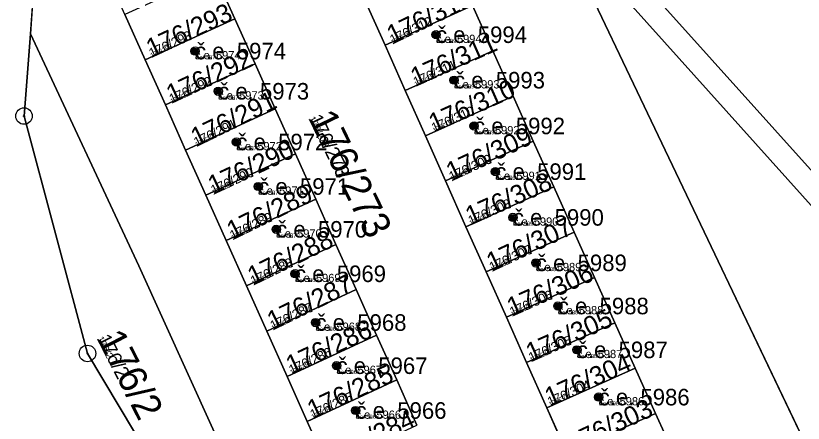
# Model space of a CAD drawing. Extents: x -759873 to -758487, y -975024 to -973516.
# Drawn here: x -759809.34 to -759761.69, y -974992.03 to -974967.38 of the extents above; entities that cross this region are included whole.
import ezdxf

# ---------------------------------------------------------------- set-up
doc = ezdxf.new("R2010")
doc.units = 0
for name, color, linetype in [('KAT_01_hranice KU', 7, 'Continuous'), ('KAT_02_hranice parcel', 7, 'Continuous'), ('KAT_03_1000_st čísla parcelní', 7, 'Continuous'), ('KAT_03_1000_čísla parcelní', 7, 'Continuous'), ('KAT_03_1000_čísla popisná', 7, 'Continuous'), ('KAT_03_250_st čísla parcelní', 7, 'Continuous'), ('KAT_03_250_čísla parcelní', 7, 'Continuous'), ('KAT_03_250_čísla popisná', 7, 'Continuous'), ('KAT_03_500_st čísla parcelní', 7, 'Continuous'), ('KAT_03_500_čísla parcelní', 7, 'Continuous'), ('KAT_03_500_čísla popisná', 7, 'Continuous'), ('KAT_07_1000_značky budov', 7, 'Continuous'), ('KAT_07_250_značky budov', 7, 'Continuous'), ('KAT_07_500_značky budov', 7, 'Continuous'), ('KAT_11_značky bodu BP', 7, 'Continuous'), ('KAT_14_plocha_budovy', 7, 'Continuous'), ('KAT_14_plocha_pozemek', 7, 'Continuous')]:
    doc.layers.add(name, color=color, linetype=linetype)

msp = doc.modelspace()

# ---------------------------------------------------------------- linework, layer by layer
at = {"layer": 'KAT_01_hranice KU'}
msp.add_lwpolyline([(-759803.85, -974931.39), (-759806.32, -974944.72), (-759806.02, -974945.39), (-759806.48, -974945.6), (-759806.7, -974946.76), (-759806.89, -974949.09), (-759807.18, -974952.49), (-759807.46, -974955.95), (-759807.76, -974956.08), (-759807.52, -974956.62), (-759808.2, -974964.8), (-759808.44, -974968.47), (-759808.84, -974973.45), (-759805, -974987.81), (-759801.16, -974994.22)], dxfattribs=at)
at = {"layer": 'KAT_02_hranice parcel'}
for p, q in [((-759776.67, -974961.64), (-759756.15, -975004.6)), ((-759808.44, -974968.47), (-759808.2, -974964.8)), ((-759797.31, -974964.83), (-759796.09, -974967.56)), ((-759786.99, -974969.17), (-759788.22, -974966.42)), ((-759781.71, -974966.77), (-759786.99, -974969.17)), ((-759781.71, -974966.77), (-759780.48, -974969.51)), ((-759801.51, -974970.04), (-759802.73, -974967.31)), ((-759796.09, -974967.56), (-759801.51, -974970.04)), ((-759796.09, -974967.56), (-759794.86, -974970.29)), ((-759785.77, -974971.91), (-759786.99, -974969.17)), ((-759780.48, -974969.51), (-759785.77, -974971.91)), ((-759780.48, -974969.51), (-759779.24, -974972.25)), ((-759800.28, -974972.78), (-759801.51, -974970.04)), ((-759794.86, -974970.29), (-759800.28, -974972.78)), ((-759794.86, -974970.29), (-759793.64, -974973.01)), ((-759784.55, -974974.65), (-759785.77, -974971.91)), ((-759779.24, -974972.25), (-759784.55, -974974.65)), ((-759779.24, -974972.25), (-759778.03, -974974.96)), ((-759799.06, -974975.51), (-759800.28, -974972.78)), ((-759793.64, -974973.01), (-759799.06, -974975.51)), ((-759793.64, -974973.01), (-759792.42, -974975.74)), ((-759783.34, -974977.36), (-759784.55, -974974.65)), ((-759778.03, -974974.96), (-759783.34, -974977.36)), ((-759778.03, -974974.96), (-759776.78, -974977.74)), ((-759797.83, -974978.23), (-759799.06, -974975.51)), ((-759792.42, -974975.74), (-759797.83, -974978.23)), ((-759792.42, -974975.74), (-759791.19, -974978.48)), ((-759782.1, -974980.14), (-759783.34, -974977.36)), ((-759776.78, -974977.74), (-759782.1, -974980.14)), ((-759776.78, -974977.74), (-759775.55, -974980.48)), ((-759796.6, -974980.98), (-759797.83, -974978.23)), ((-759791.19, -974978.48), (-759796.6, -974980.98)), ((-759791.19, -974978.48), (-759789.97, -974981.21)), ((-759780.87, -974982.88), (-759782.1, -974980.14)), ((-759775.55, -974980.48), (-759780.87, -974982.88)), ((-759775.55, -974980.48), (-759774.32, -974983.22)), ((-759795.38, -974983.71), (-759796.6, -974980.98)), ((-759789.97, -974981.21), (-759795.38, -974983.71)), ((-759789.97, -974981.21), (-759788.74, -974983.95)), ((-759779.65, -974985.62), (-759780.87, -974982.88)), ((-759774.32, -974983.22), (-759779.65, -974985.62)), ((-759774.32, -974983.22), (-759773.09, -974985.95)), ((-759794.15, -974986.46), (-759795.38, -974983.71)), ((-759788.74, -974983.95), (-759794.15, -974986.46)), ((-759788.74, -974983.95), (-759787.51, -974986.7)), ((-759778.44, -974988.35), (-759779.65, -974985.62)), ((-759773.09, -974985.95), (-759778.44, -974988.35)), ((-759773.09, -974985.95), (-759771.86, -974988.69)), ((-759792.91, -974989.21), (-759794.15, -974986.46)), ((-759787.51, -974986.7), (-759792.91, -974989.21)), ((-759787.51, -974986.7), (-759786.29, -974989.41)), ((-759777.21, -974991.09), (-759778.44, -974988.35)), ((-759771.86, -974988.69), (-759777.21, -974991.09)), ((-759771.86, -974988.69), (-759770.63, -974991.44)), ((-759791.7, -974991.92), (-759792.91, -974989.21)), ((-759786.29, -974989.41), (-759791.7, -974991.92)), ((-759786.29, -974989.41), (-759785.07, -974992.14)), ((-759775.98, -974993.84), (-759777.21, -974991.09)), ((-759770.63, -974991.44), (-759775.98, -974993.84)), ((-759770.63, -974991.44), (-759769.39, -974994.19)), ((-759790.47, -974994.66), (-759791.7, -974991.92))]:
    msp.add_line(p, q, dxfattribs=at)
for points in [[(-759776.67, -974961.64), (-759760.85, -974979.26), (-759749.8, -974991.38)], [(-759740.23, -974999.88), (-759748.8, -974990.42), (-759759.81, -974978.29), (-759770.81, -974966.03)], [(-759801.16, -974994.22), (-759805, -974987.81), (-759808.84, -974973.45), (-759808.44, -974968.47)], [(-759786.86, -975015.6), (-759801.9, -974982.51), (-759808.44, -974968.47)]]:
    msp.add_lwpolyline(points, dxfattribs=at)
at = {"layer": 'KAT_03_1000_čísla popisná'}
for centre in [(-759783.91, -974968.53), (-759798.49, -974969.52), (-759782.82, -974971.28), (-759797.09, -974971.95), (-759781.61, -974974.05), (-759795.99, -974975.02), (-759780.32, -974976.81), (-759794.67, -974977.71), (-759779.26, -974979.58), (-759793.58, -974980.3), (-759777.87, -974982.33), (-759792.44, -974982.99), (-759776.54, -974984.94), (-759791.2, -974985.94), (-759775.39, -974987.59), (-759789.93, -974988.55), (-759774.07, -974990.45), (-759788.78, -974991.26)]:
    msp.add_circle(centre, 0.25, dxfattribs=at)
at = {"layer": 'KAT_03_250_čísla popisná'}
for centre in [(-759783.91, -974968.53), (-759798.49, -974969.52), (-759782.82, -974971.28), (-759797.09, -974971.95), (-759781.61, -974974.05), (-759795.99, -974975.02), (-759780.32, -974976.81), (-759794.67, -974977.71), (-759779.26, -974979.58), (-759793.58, -974980.3), (-759777.87, -974982.33), (-759792.44, -974982.99), (-759776.54, -974984.94), (-759791.2, -974985.94), (-759775.39, -974987.59), (-759789.93, -974988.55), (-759774.07, -974990.45), (-759788.78, -974991.26)]:
    msp.add_circle(centre, 0.0625, dxfattribs=at)
at = {"layer": 'KAT_03_500_čísla popisná'}
for centre in [(-759783.91, -974968.53), (-759798.49, -974969.52), (-759782.82, -974971.28), (-759797.09, -974971.95), (-759781.61, -974974.05), (-759795.99, -974975.02), (-759780.32, -974976.81), (-759794.67, -974977.71), (-759779.26, -974979.58), (-759793.58, -974980.3), (-759777.87, -974982.33), (-759792.44, -974982.99), (-759776.54, -974984.94), (-759791.2, -974985.94), (-759775.39, -974987.59), (-759789.93, -974988.55), (-759774.07, -974990.45), (-759788.78, -974991.26)]:
    msp.add_circle(centre, 0.125, dxfattribs=at)
at = {"layer": 'KAT_07_1000_značky budov'}
for centre in [(-759783.917, -974968.529), (-759798.497, -974969.519), (-759782.827, -974971.279), (-759797.097, -974971.949), (-759781.617, -974974.049), (-759795.997, -974975.019), (-759780.327, -974976.809), (-759794.677, -974977.709), (-759779.267, -974979.579), (-759793.587, -974980.299), (-759777.877, -974982.329), (-759792.447, -974982.989), (-759776.547, -974984.939), (-759791.207, -974985.939), (-759775.397, -974987.589), (-759789.937, -974988.549), (-759774.077, -974990.449), (-759788.787, -974991.259)]:
    msp.add_circle(centre, 0.175, dxfattribs=at)
at = {"layer": 'KAT_07_250_značky budov'}
for centre in [(-759783.912, -974968.53), (-759798.492, -974969.52), (-759782.822, -974971.28), (-759797.092, -974971.95), (-759781.612, -974974.05), (-759795.992, -974975.02), (-759780.322, -974976.81), (-759794.672, -974977.71), (-759779.262, -974979.58), (-759793.582, -974980.3), (-759777.872, -974982.33), (-759792.442, -974982.99), (-759776.542, -974984.94), (-759791.202, -974985.94), (-759775.392, -974987.59), (-759789.932, -974988.55), (-759774.072, -974990.45), (-759788.782, -974991.26)]:
    msp.add_circle(centre, 0.0437, dxfattribs=at)
at = {"layer": 'KAT_07_500_značky budov'}
for centre in [(-759783.913, -974968.53), (-759798.493, -974969.52), (-759782.823, -974971.28), (-759797.093, -974971.95), (-759781.613, -974974.05), (-759795.993, -974975.02), (-759780.323, -974976.81), (-759794.673, -974977.71), (-759779.263, -974979.58), (-759793.583, -974980.3), (-759777.873, -974982.33), (-759792.443, -974982.99), (-759776.543, -974984.94), (-759791.203, -974985.94), (-759775.393, -974987.59), (-759789.933, -974988.55), (-759774.073, -974990.45), (-759788.783, -974991.26)]:
    msp.add_circle(centre, 0.0875, dxfattribs=at)
at = {"layer": 'KAT_11_značky bodu BP'}
for centre, radius in [((-759808.84, -974973.45), 0.5), ((-759808.84, -974973.45), 0.0303), ((-759805, -974987.81), 0.5), ((-759805, -974987.81), 0.0303)]:
    msp.add_circle(centre, radius, dxfattribs=at)
at = {"layer": 'KAT_14_plocha_budovy'}
for points in [[(-759786.99, -974969.17), (-759781.71, -974966.77), (-759782.94, -974964.02), (-759788.22, -974966.42)], [(-759802.73, -974967.31), (-759801.51, -974970.04), (-759796.09, -974967.56), (-759797.31, -974964.83)], [(-759785.77, -974971.91), (-759780.48, -974969.51), (-759781.71, -974966.77), (-759786.99, -974969.17)], [(-759801.51, -974970.04), (-759800.28, -974972.78), (-759794.86, -974970.29), (-759796.09, -974967.56)], [(-759784.55, -974974.65), (-759779.24, -974972.25), (-759780.48, -974969.51), (-759785.77, -974971.91)], [(-759800.28, -974972.78), (-759799.06, -974975.51), (-759793.64, -974973.01), (-759794.86, -974970.29)], [(-759779.24, -974972.25), (-759784.55, -974974.65), (-759783.34, -974977.36), (-759778.03, -974974.96)], [(-759799.06, -974975.51), (-759797.83, -974978.23), (-759792.42, -974975.74), (-759793.64, -974973.01)], [(-759782.1, -974980.14), (-759776.78, -974977.74), (-759778.03, -974974.96), (-759783.34, -974977.36)], [(-759792.42, -974975.74), (-759797.83, -974978.23), (-759796.6, -974980.98), (-759791.19, -974978.48)], [(-759780.87, -974982.88), (-759775.55, -974980.48), (-759776.78, -974977.74), (-759782.1, -974980.14)], [(-759796.6, -974980.98), (-759795.38, -974983.71), (-759789.97, -974981.21), (-759791.19, -974978.48)], [(-759779.65, -974985.62), (-759774.32, -974983.22), (-759775.55, -974980.48), (-759780.87, -974982.88)], [(-759795.38, -974983.71), (-759794.15, -974986.46), (-759788.74, -974983.95), (-759789.97, -974981.21)], [(-759779.65, -974985.62), (-759778.44, -974988.35), (-759773.09, -974985.95), (-759774.32, -974983.22)], [(-759794.15, -974986.46), (-759792.91, -974989.21), (-759787.51, -974986.7), (-759788.74, -974983.95)], [(-759778.44, -974988.35), (-759777.21, -974991.09), (-759771.86, -974988.69), (-759773.09, -974985.95)], [(-759792.91, -974989.21), (-759791.7, -974991.92), (-759786.29, -974989.41), (-759787.51, -974986.7)], [(-759775.98, -974993.84), (-759770.63, -974991.44), (-759771.86, -974988.69), (-759777.21, -974991.09)], [(-759786.29, -974989.41), (-759791.7, -974991.92), (-759790.47, -974994.66), (-759785.07, -974992.14)], [(-759775.98, -974993.84), (-759774.76, -974996.59), (-759769.39, -974994.19), (-759770.63, -974991.44)]]:
    msp.add_lwpolyline(points, close=True, dxfattribs=at)
at = {"layer": 'KAT_14_plocha_pozemek'}
for points in [[(-759803.85, -974931.39), (-759806.32, -974944.72), (-759806.02, -974945.39), (-759804.79, -974948.14), (-759803.57, -974950.86), (-759802.34, -974953.61), (-759801.13, -974956.31), (-759799.77, -974959.35), (-759798.54, -974962.09), (-759797.31, -974964.83), (-759796.09, -974967.56), (-759794.86, -974970.29), (-759793.64, -974973.01), (-759792.42, -974975.74), (-759791.19, -974978.48), (-759789.97, -974981.21), (-759788.74, -974983.95), (-759787.51, -974986.7), (-759786.29, -974989.41), (-759785.07, -974992.14)], [(-759756.15, -975004.6), (-759776.67, -974961.64), (-759778.87, -974959.18), (-759782.83, -974956.39), (-759784.21, -974954.04), (-759795.39, -974932.77)], [(-759795.23, -974936.66), (-759794.01, -974939.39), (-759792.78, -974942.12), (-759791.55, -974944.86), (-759790.31, -974947.6), (-759789.09, -974950.33), (-759787.87, -974953.05), (-759786.64, -974955.8), (-759785.41, -974958.53), (-759784.17, -974961.28), (-759782.94, -974964.02), (-759781.71, -974966.77), (-759780.48, -974969.51), (-759779.24, -974972.25), (-759778.03, -974974.96), (-759776.78, -974977.74), (-759775.55, -974980.48), (-759774.32, -974983.22), (-759773.09, -974985.95), (-759771.86, -974988.69), (-759770.63, -974991.44), (-759769.39, -974994.19)], [(-759775.98, -974993.84), (-759777.21, -974991.09), (-759778.44, -974988.35), (-759779.65, -974985.62), (-759780.87, -974982.88), (-759782.1, -974980.14), (-759783.34, -974977.36), (-759784.55, -974974.65), (-759785.77, -974971.91), (-759786.99, -974969.17), (-759788.22, -974966.42), (-759789.44, -974963.68), (-759790.67, -974960.93), (-759791.89, -974958.2), (-759793.12, -974955.45), (-759794.33, -974952.73), (-759795.55, -974950.01), (-759796.77, -974947.26), (-759797.99, -974944.52), (-759799.22, -974941.79), (-759800.43, -974939.06)], [(-759790.47, -974994.66), (-759791.7, -974991.92), (-759792.91, -974989.21), (-759794.15, -974986.46), (-759795.38, -974983.71), (-759796.6, -974980.98), (-759797.83, -974978.23), (-759799.06, -974975.51), (-759800.28, -974972.78), (-759801.51, -974970.04), (-759802.73, -974967.31), (-759803.96, -974964.56), (-759805.19, -974961.83), (-759806.55, -974958.78), (-759807.52, -974956.62), (-759808.2, -974964.8), (-759808.44, -974968.47), (-759801.9, -974982.51), (-759786.86, -975015.6)]]:
    msp.add_lwpolyline(points, dxfattribs=at)
for points in [[(-759748.8, -974990.42), (-759759.81, -974978.29), (-759770.81, -974966.03), (-759772.94, -974963.45), (-759777.02, -974959.04), (-759777.17, -974957.17), (-759779.21, -974956.31), (-759776.67, -974961.64), (-759760.85, -974979.26), (-759749.8, -974991.38), (-759741.85, -975000.36), (-759740.23, -974999.88)], [(-759753.64, -975003.86), (-759752.46, -975003.34), (-759756.88, -974995.21), (-759749.8, -974991.38), (-759760.85, -974979.26), (-759776.67, -974961.64), (-759756.15, -975004.6)], [(-759727.3, -974996.05), (-759719.75, -974996.3), (-759712.2, -974997), (-759687.1, -974995.48), (-759695.75, -974993.4), (-759714.25, -974985.59), (-759715.79, -974989.44), (-759724.08, -974985.84), (-759722.49, -974982.07), (-759750.27, -974970.29), (-759752.01, -974974.08), (-759760.18, -974970.6), (-759758.63, -974966.73), (-759769.24, -974962.19), (-759770.81, -974966.03), (-759759.81, -974978.29), (-759748.8, -974990.42), (-759740.23, -974999.88)], [(-759788.22, -974966.42), (-759786.99, -974969.17), (-759781.71, -974966.77), (-759782.94, -974964.02)], [(-759802.73, -974967.31), (-759801.51, -974970.04), (-759796.09, -974967.56), (-759797.31, -974964.83)], [(-759786.99, -974969.17), (-759785.77, -974971.91), (-759780.48, -974969.51), (-759781.71, -974966.77)], [(-759801.51, -974970.04), (-759800.28, -974972.78), (-759794.86, -974970.29), (-759796.09, -974967.56)], [(-759805, -974987.81), (-759801.16, -974994.22), (-759791.36, -975009.38), (-759786.86, -975015.6), (-759801.9, -974982.51), (-759808.44, -974968.47), (-759808.84, -974973.45)], [(-759785.77, -974971.91), (-759784.55, -974974.65), (-759779.24, -974972.25), (-759780.48, -974969.51)], [(-759800.28, -974972.78), (-759799.06, -974975.51), (-759793.64, -974973.01), (-759794.86, -974970.29)], [(-759784.55, -974974.65), (-759783.34, -974977.36), (-759778.03, -974974.96), (-759779.24, -974972.25)], [(-759799.06, -974975.51), (-759797.83, -974978.23), (-759792.42, -974975.74), (-759793.64, -974973.01)], [(-759783.34, -974977.36), (-759782.1, -974980.14), (-759776.78, -974977.74), (-759778.03, -974974.96)], [(-759797.83, -974978.23), (-759796.6, -974980.98), (-759791.19, -974978.48), (-759792.42, -974975.74)], [(-759782.1, -974980.14), (-759780.87, -974982.88), (-759775.55, -974980.48), (-759776.78, -974977.74)], [(-759796.6, -974980.98), (-759795.38, -974983.71), (-759789.97, -974981.21), (-759791.19, -974978.48)], [(-759780.87, -974982.88), (-759779.65, -974985.62), (-759774.32, -974983.22), (-759775.55, -974980.48)], [(-759795.38, -974983.71), (-759794.15, -974986.46), (-759788.74, -974983.95), (-759789.97, -974981.21)], [(-759779.65, -974985.62), (-759778.44, -974988.35), (-759773.09, -974985.95), (-759774.32, -974983.22)], [(-759794.15, -974986.46), (-759792.91, -974989.21), (-759787.51, -974986.7), (-759788.74, -974983.95)], [(-759778.44, -974988.35), (-759777.21, -974991.09), (-759771.86, -974988.69), (-759773.09, -974985.95)], [(-759792.91, -974989.21), (-759791.7, -974991.92), (-759786.29, -974989.41), (-759787.51, -974986.7)], [(-759777.21, -974991.09), (-759775.98, -974993.84), (-759770.63, -974991.44), (-759771.86, -974988.69)], [(-759791.7, -974991.92), (-759790.47, -974994.66), (-759785.07, -974992.14), (-759786.29, -974989.41)], [(-759775.98, -974993.84), (-759774.76, -974996.59), (-759769.39, -974994.19), (-759770.63, -974991.44)]]:
    msp.add_lwpolyline(points, close=True, dxfattribs=at)

# ---------------------------------------------------------------- texts
at = {"layer": 'KAT_03_1000_st čísla parcelní'}
for s, rotation, p in [('176/312', 26, (-759786.54, -974969.122)), ('176/293', 25, (-759801.119, -974969.936)), ('176/311', 24, (-759785.138, -974971.68)), ('176/292', 25, (-759799.899, -974972.706)), ('176/310', 24, (-759784.038, -974974.46)), ('176/291', 26, (-759798.4, -974975.322)), ('176/309', 25, (-759782.969, -974977.406)), ('176/290', 25, (-759797.379, -974978.216)), ('176/308', 24, (-759781.818, -974980.07)), ('176/289', 26, (-759796.22, -974980.962)), ('176/307', 25, (-759780.529, -974982.876)), ('176/288', 26, (-759794.97, -974983.712)), ('176/306', 24, (-759779.308, -974985.59)), ('176/287', 26, (-759793.78, -974986.422)), ('176/305', 24, (-759778.158, -974988.34)), ('176/286', 25, (-759792.659, -974989.096)), ('176/304', 24, (-759777.018, -974991.03)), ('176/285', 25, (-759791.369, -974991.796)), ('176/303', 25, (-759775.679, -974993.866)), ('176/284', 25, (-759790.069, -974994.516))]:
    msp.add_text(s, height=1.14, rotation=rotation, dxfattribs=at).set_placement(p)
at = {"layer": 'KAT_03_1000_čísla parcelní'}
for s, rotation, p in [('176/273', 296, (-759791.643, -974973.592)), ('176/2', 297, (-759804.447, -974986.905))]:
    msp.add_text(s, height=1.7, rotation=rotation, dxfattribs=at).set_placement(p)
at = {"layer": 'KAT_03_1000_čísla popisná'}
for s, p in [('č.e. 5994', (-759783.91, -974969.03)), ('č.e. 5974', (-759798.49, -974970.02)), ('č.e. 5993', (-759782.82, -974971.78)), ('č.e. 5973', (-759797.09, -974972.45)), ('č.e. 5992', (-759781.61, -974974.55)), ('č.e. 5972', (-759795.99, -974975.52)), ('č.e. 5991', (-759780.32, -974977.31)), ('č.e. 5971', (-759794.67, -974978.21)), ('č.e. 5990', (-759779.26, -974980.08)), ('č.e. 5970', (-759793.58, -974980.8)), ('č.e. 5989', (-759777.87, -974982.83)), ('č.e. 5969', (-759792.44, -974983.49)), ('č.e. 5988', (-759776.54, -974985.44)), ('č.e. 5968', (-759791.2, -974986.44)), ('č.e. 5987', (-759775.39, -974988.09)), ('č.e. 5967', (-759789.93, -974989.05)), ('č.e. 5986', (-759774.07, -974990.95)), ('č.e. 5966', (-759788.78, -974991.76))]:
    msp.add_text(s, height=1, dxfattribs=at).set_placement(p)
at = {"layer": 'KAT_03_250_st čísla parcelní'}
for s, rotation, p in [('176/312', 26, (-759786.54, -974969.122)), ('176/293', 25, (-759801.119, -974969.936)), ('176/311', 24, (-759785.138, -974971.68)), ('176/292', 25, (-759799.899, -974972.706)), ('176/310', 24, (-759784.038, -974974.46)), ('176/291', 26, (-759798.4, -974975.322)), ('176/309', 25, (-759782.969, -974977.406)), ('176/290', 25, (-759797.379, -974978.216)), ('176/308', 24, (-759781.818, -974980.07)), ('176/289', 26, (-759796.22, -974980.962)), ('176/307', 25, (-759780.529, -974982.876)), ('176/288', 26, (-759794.97, -974983.712)), ('176/306', 24, (-759779.308, -974985.59)), ('176/287', 26, (-759793.78, -974986.422)), ('176/305', 24, (-759778.158, -974988.34)), ('176/286', 25, (-759792.659, -974989.096)), ('176/304', 24, (-759777.018, -974991.03)), ('176/285', 25, (-759791.369, -974991.796))]:
    msp.add_text(s, height=0.285, rotation=rotation, dxfattribs=at).set_placement(p)
at = {"layer": 'KAT_03_250_čísla parcelní'}
for s, rotation, p in [('176/273', 296, (-759791.643, -974973.592)), ('176/2', 297, (-759804.447, -974986.905))]:
    msp.add_text(s, height=0.425, rotation=rotation, dxfattribs=at).set_placement(p)
at = {"layer": 'KAT_03_250_čísla popisná'}
for s, p in [('č.e. 5994', (-759783.91, -974969.03)), ('č.e. 5974', (-759798.49, -974970.02)), ('č.e. 5993', (-759782.82, -974971.78)), ('č.e. 5973', (-759797.09, -974972.45)), ('č.e. 5992', (-759781.61, -974974.55)), ('č.e. 5972', (-759795.99, -974975.52)), ('č.e. 5991', (-759780.32, -974977.31)), ('č.e. 5971', (-759794.67, -974978.21)), ('č.e. 5990', (-759779.26, -974980.08)), ('č.e. 5970', (-759793.58, -974980.8)), ('č.e. 5989', (-759777.87, -974982.83)), ('č.e. 5969', (-759792.44, -974983.49)), ('č.e. 5988', (-759776.54, -974985.44)), ('č.e. 5968', (-759791.2, -974986.44)), ('č.e. 5987', (-759775.39, -974988.09)), ('č.e. 5967', (-759789.93, -974989.05)), ('č.e. 5986', (-759774.07, -974990.95)), ('č.e. 5966', (-759788.78, -974991.76))]:
    msp.add_text(s, height=0.25, dxfattribs=at).set_placement(p)
at = {"layer": 'KAT_03_500_st čísla parcelní'}
for s, rotation, p in [('176/312', 26, (-759786.54, -974969.122)), ('176/293', 25, (-759801.119, -974969.936)), ('176/311', 24, (-759785.138, -974971.68)), ('176/292', 25, (-759799.899, -974972.706)), ('176/310', 24, (-759784.038, -974974.46)), ('176/291', 26, (-759798.4, -974975.322)), ('176/309', 25, (-759782.969, -974977.406)), ('176/290', 25, (-759797.379, -974978.216)), ('176/308', 24, (-759781.818, -974980.07)), ('176/289', 26, (-759796.22, -974980.962)), ('176/307', 25, (-759780.529, -974982.876)), ('176/288', 26, (-759794.97, -974983.712)), ('176/306', 24, (-759779.308, -974985.59)), ('176/287', 26, (-759793.78, -974986.422)), ('176/305', 24, (-759778.158, -974988.34)), ('176/286', 25, (-759792.659, -974989.096)), ('176/304', 24, (-759777.018, -974991.03)), ('176/285', 25, (-759791.369, -974991.796))]:
    msp.add_text(s, height=0.57, rotation=rotation, dxfattribs=at).set_placement(p)
at = {"layer": 'KAT_03_500_čísla parcelní'}
for s, rotation, p in [('176/273', 296, (-759791.643, -974973.592)), ('176/2', 297, (-759804.447, -974986.905))]:
    msp.add_text(s, height=0.85, rotation=rotation, dxfattribs=at).set_placement(p)
at = {"layer": 'KAT_03_500_čísla popisná'}
for s, p in [('č.e. 5994', (-759783.91, -974969.03)), ('č.e. 5974', (-759798.49, -974970.02)), ('č.e. 5993', (-759782.82, -974971.78)), ('č.e. 5973', (-759797.09, -974972.45)), ('č.e. 5992', (-759781.61, -974974.55)), ('č.e. 5972', (-759795.99, -974975.52)), ('č.e. 5991', (-759780.32, -974977.31)), ('č.e. 5971', (-759794.67, -974978.21)), ('č.e. 5990', (-759779.26, -974980.08)), ('č.e. 5970', (-759793.58, -974980.8)), ('č.e. 5989', (-759777.87, -974982.83)), ('č.e. 5969', (-759792.44, -974983.49)), ('č.e. 5988', (-759776.54, -974985.44)), ('č.e. 5968', (-759791.2, -974986.44)), ('č.e. 5987', (-759775.39, -974988.09)), ('č.e. 5967', (-759789.93, -974989.05)), ('č.e. 5986', (-759774.07, -974990.95)), ('č.e. 5966', (-759788.78, -974991.76))]:
    msp.add_text(s, height=0.5, dxfattribs=at).set_placement(p)

doc.saveas('drawing.dxf')
